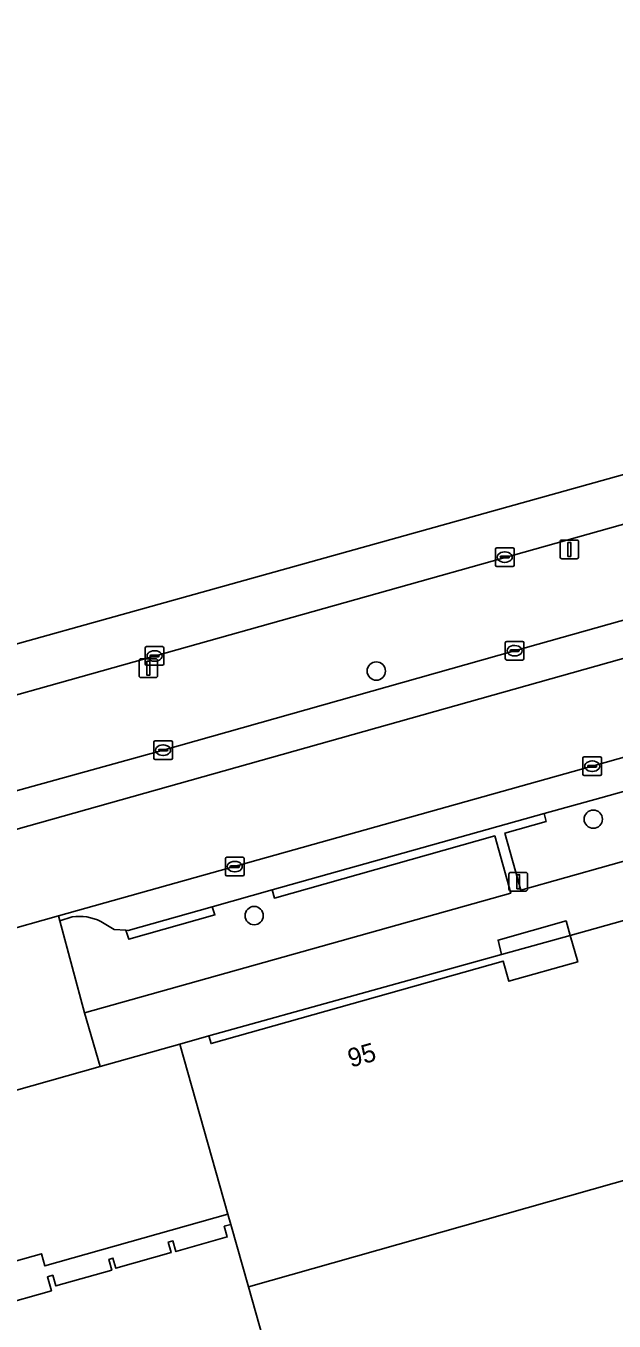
# Model space of a CAD drawing. Extents: x 159680 to 160786, y 387323 to 388340.
# Drawn here: x 159778.2 to 159809.7, y 388163.8 to 388233.1 of the extents above; entities that cross this region are included whole.
import ezdxf

# ---------------------------------------------------------------- set-up
doc = ezdxf.new("R2010")
doc.units = 0
for name, color, linetype in [('IMGEO_Berm_groen', 7, 'Continuous'), ('IMGEO_Boom', 7, 'Continuous'), ('IMGEO_Groenvoorziening', 7, 'Continuous'), ('IMGEO_Kolk', 7, 'Continuous'), ('IMGEO_Lichtmast', 7, 'Continuous'), ('IMGEO_Pand', 7, 'Continuous'), ('IMGEO_Pand_nummerreeks', 7, 'Continuous'), ('IMGEO_Pand_overbouw', 7, 'Continuous'), ('IMGEO_Parkeervlak_open', 7, 'Continuous'), ('IMGEO_Rijbaan_lokaal_open', 7, 'Continuous'), ('IMGEO_Rijbaan_regionaal_gesloten', 7, 'Continuous'), ('IMGEO_Verkeersbordpaal', 7, 'Continuous'), ('IMGEO_Voetpad_open', 7, 'Continuous')]:
    doc.layers.add(name, color=color, linetype=linetype)

msp = doc.modelspace()

# ---------------------------------------------------------------- linework, layer by layer
at = {"layer": 'IMGEO_Berm_groen'}
for points in [[(159920.962, 388232.427), (159919.6, 388237.172), (159716.247, 388179.993)], [(159752.583, 388183.497), (159752.167, 388185.012), (159768.684, 388189.645), (159785.592, 388194.317), (159804.409, 388199.642), (159825.126, 388205.478), (159845.859, 388211.321), (159866.616, 388217.142), (159886.436, 388222.745), (159891.938, 388224.314)]]:
    msp.add_lwpolyline(points, dxfattribs=at)
at = {"layer": 'IMGEO_Boom'}
for centre in [(159797.001, 388198.552), (159808.618, 388190.623), (159790.464, 388185.463)]:
    msp.add_circle(centre, 0.489, dxfattribs=at)
at = {"layer": 'IMGEO_Groenvoorziening'}
for points in [[(159819.69, 388191.76), (159819.005, 388194.105), (159810.488, 388191.713), (159810.361, 388192.138), (159809.024, 388191.774), (159805.984, 388190.92), (159806.089, 388190.5), (159803.886, 388189.879), (159804.744, 388186.824), (159819.205, 388190.886)], [(159780.728, 388185.388), (159780.065, 388185.175), (159781.381, 388180.261), (159804.201, 388186.672), (159803.344, 388189.726), (159791.55, 388186.398), (159791.436, 388186.838), (159788.22, 388185.935), (159788.364, 388185.498), (159783.745, 388184.195), (159783.589, 388184.683), (159782.973, 388184.723), (159782.255, 388185.142)]]:
    msp.add_lwpolyline(points, dxfattribs=at)
msp.add_arc((159781.126, 388182.997), 2.424, 62.24403, 99.45251, dxfattribs=at)
at = {"layer": 'IMGEO_Kolk'}
for p, q in [((159803.381, 388204.227), (159803.381, 388205.079)), ((159803.456, 388205.153), (159804.308, 388205.153)), ((159803.869, 388204.933), (159803.894, 388204.933)), ((159804.382, 388205.079), (159804.382, 388204.227)), ((159804.308, 388204.153), (159803.456, 388204.153)), ((159803.64, 388204.647), (159803.64, 388204.659)), ((159804.078, 388204.61), (159803.68, 388204.61)), ((159803.683, 388204.696), (159804.081, 388204.696)), ((159803.892, 388204.373), (159803.867, 388204.373)), ((159804.124, 388204.659), (159804.124, 388204.647)), ((159803.908, 388199.217), (159803.908, 388200.069)), ((159803.983, 388200.143), (159804.835, 388200.143)), ((159804.396, 388199.923), (159804.421, 388199.923)), ((159804.909, 388200.069), (159804.909, 388199.217)), ((159784.629, 388198.935), (159784.629, 388199.787)), ((159784.704, 388199.861), (159785.556, 388199.861)), ((159784.888, 388199.355), (159784.888, 388199.367)), ((159785.326, 388199.318), (159784.928, 388199.318)), ((159784.931, 388199.404), (159785.329, 388199.404)), ((159785.117, 388199.641), (159785.142, 388199.641)), ((159785.372, 388199.367), (159785.372, 388199.355)), ((159785.63, 388199.787), (159785.63, 388198.935)), ((159804.167, 388199.637), (159804.167, 388199.649)), ((159804.605, 388199.6), (159804.207, 388199.6)), ((159804.21, 388199.686), (159804.608, 388199.686)), ((159804.419, 388199.363), (159804.394, 388199.363)), ((159804.651, 388199.649), (159804.651, 388199.637)), ((159785.556, 388198.861), (159784.704, 388198.861)), ((159785.14, 388199.081), (159785.115, 388199.081)), ((159804.835, 388199.143), (159803.983, 388199.143)), ((159785.09, 388193.892), (159785.09, 388194.744)), ((159785.165, 388194.818), (159786.017, 388194.818)), ((159785.392, 388194.361), (159785.79, 388194.361)), ((159785.578, 388194.598), (159785.603, 388194.598)), ((159786.091, 388194.744), (159786.091, 388193.892)), ((159786.017, 388193.818), (159785.165, 388193.818)), ((159785.349, 388194.312), (159785.349, 388194.324)), ((159785.787, 388194.275), (159785.389, 388194.275)), ((159785.601, 388194.038), (159785.576, 388194.038)), ((159785.833, 388194.324), (159785.833, 388194.312)), ((159808.061, 388193.033), (159808.061, 388193.885)), ((159808.136, 388193.959), (159808.988, 388193.959)), ((159808.549, 388193.739), (159808.574, 388193.739)), ((159809.062, 388193.885), (159809.062, 388193.033)), ((159808.988, 388192.959), (159808.136, 388192.959)), ((159808.32, 388193.453), (159808.32, 388193.465)), ((159808.758, 388193.416), (159808.36, 388193.416)), ((159808.363, 388193.502), (159808.761, 388193.502)), ((159808.572, 388193.179), (159808.547, 388193.179)), ((159808.804, 388193.465), (159808.804, 388193.453)), ((159788.927, 388187.659), (159788.927, 388188.511)), ((159789.002, 388188.585), (159789.854, 388188.585)), ((159789.229, 388188.128), (159789.627, 388188.128)), ((159789.415, 388188.365), (159789.44, 388188.365)), ((159789.928, 388188.511), (159789.928, 388187.659)), ((159789.854, 388187.585), (159789.002, 388187.585)), ((159789.186, 388188.079), (159789.186, 388188.091)), ((159789.624, 388188.042), (159789.226, 388188.042)), ((159789.438, 388187.805), (159789.413, 388187.805)), ((159789.67, 388188.091), (159789.67, 388188.079))]:
    msp.add_line(p, q, dxfattribs=at)
for points in [[(159803.381, 388204.227), (159803.381, 388205.079)], [(159803.456, 388205.153), (159804.308, 388205.153)], [(159804.382, 388205.079), (159804.382, 388204.227)], [(159804.308, 388204.153), (159803.456, 388204.153)], [(159803.908, 388199.217), (159803.908, 388200.069)], [(159803.983, 388200.143), (159804.835, 388200.143)], [(159804.909, 388200.069), (159804.909, 388199.217)], [(159784.629, 388198.935), (159784.629, 388199.787)], [(159784.704, 388199.861), (159785.556, 388199.861)], [(159785.63, 388199.787), (159785.63, 388198.935)], [(159785.556, 388198.861), (159784.704, 388198.861)], [(159804.835, 388199.143), (159803.983, 388199.143)], [(159785.09, 388193.892), (159785.09, 388194.744)], [(159785.165, 388194.818), (159786.017, 388194.818)], [(159786.091, 388194.744), (159786.091, 388193.892)], [(159786.017, 388193.818), (159785.165, 388193.818)], [(159808.061, 388193.033), (159808.061, 388193.885)], [(159808.136, 388193.959), (159808.988, 388193.959)], [(159809.062, 388193.885), (159809.062, 388193.033)], [(159808.988, 388192.959), (159808.136, 388192.959)], [(159788.927, 388187.659), (159788.927, 388188.511)], [(159789.002, 388188.585), (159789.854, 388188.585)], [(159789.928, 388188.511), (159789.928, 388187.659)], [(159789.854, 388187.585), (159789.002, 388187.585)]]:
    msp.add_lwpolyline(points, dxfattribs=at)
for centre, radius, start, end in [((159803.458, 388205.077), 0.0765, 91.55205, 178.44795), ((159803.458, 388205.077), 0.0765, 91.55205, 178.44795), ((159804.306, 388205.077), 0.0765, 1.55205, 88.44795), ((159804.306, 388205.077), 0.0765, 1.55205, 88.44795), ((159803.458, 388204.229), 0.0765, 181.55205, 268.44795), ((159803.458, 388204.229), 0.0765, 181.55205, 268.44795), ((159803.68, 388204.656), 0.0403, 85.87752, 175.75265), ((159803.677, 388204.646), 0.0366, 178.93798, 274.71019), ((159804.081, 388204.653), 0.043, 264.86636, 352.45326), ((159804.085, 388204.658), 0.0386, 1.73085, 96.63898), ((159804.306, 388204.229), 0.0765, 271.55205, 358.44795), ((159804.306, 388204.229), 0.0765, 271.55205, 358.44795), ((159803.985, 388200.067), 0.0765, 91.55205, 178.44795), ((159803.985, 388200.067), 0.0765, 91.55205, 178.44795), ((159804.833, 388200.067), 0.0765, 1.55205, 88.44795), ((159804.833, 388200.067), 0.0765, 1.55205, 88.44795), ((159784.706, 388199.785), 0.0765, 91.55205, 178.44795), ((159784.706, 388199.785), 0.0765, 91.55205, 178.44795), ((159784.928, 388199.364), 0.0403, 85.87752, 175.75265), ((159784.925, 388199.354), 0.0366, 178.93798, 274.71019), ((159785.329, 388199.361), 0.043, 264.86636, 352.45326), ((159785.333, 388199.366), 0.0386, 1.73085, 96.63898), ((159785.554, 388199.785), 0.0765, 1.55205, 88.44795), ((159785.554, 388199.785), 0.0765, 1.55205, 88.44795), ((159803.985, 388199.219), 0.0765, 181.55205, 268.44795), ((159803.985, 388199.219), 0.0765, 181.55205, 268.44795), ((159804.207, 388199.646), 0.0403, 85.87752, 175.75265), ((159804.204, 388199.636), 0.0366, 178.93798, 274.71019), ((159804.608, 388199.643), 0.043, 264.86636, 352.45326), ((159804.612, 388199.648), 0.0386, 1.73085, 96.63898), ((159804.833, 388199.219), 0.0765, 271.55205, 358.44795), ((159804.833, 388199.219), 0.0765, 271.55205, 358.44795), ((159784.706, 388198.937), 0.0765, 181.55205, 268.44795), ((159784.706, 388198.937), 0.0765, 181.55205, 268.44795), ((159785.554, 388198.937), 0.0765, 271.55205, 358.44795), ((159785.554, 388198.937), 0.0765, 271.55205, 358.44795), ((159785.167, 388194.742), 0.0765, 91.55205, 178.44795), ((159785.167, 388194.742), 0.0765, 91.55205, 178.44795), ((159785.389, 388194.321), 0.0403, 85.87752, 175.75265), ((159785.794, 388194.323), 0.0386, 1.73085, 96.63898), ((159786.015, 388194.742), 0.0765, 1.55205, 88.44795), ((159786.015, 388194.742), 0.0765, 1.55205, 88.44795), ((159785.167, 388193.894), 0.0765, 181.55205, 268.44795), ((159785.167, 388193.894), 0.0765, 181.55205, 268.44795), ((159785.386, 388194.311), 0.0366, 178.93798, 274.71019), ((159785.79, 388194.318), 0.043, 264.86636, 352.45326), ((159786.015, 388193.894), 0.0765, 271.55205, 358.44795), ((159786.015, 388193.894), 0.0765, 271.55205, 358.44795), ((159808.138, 388193.883), 0.0765, 91.55205, 178.44795), ((159808.138, 388193.883), 0.0765, 91.55205, 178.44795), ((159808.986, 388193.883), 0.0765, 1.55205, 88.44795), ((159808.986, 388193.883), 0.0765, 1.55205, 88.44795), ((159808.138, 388193.035), 0.0765, 181.55205, 268.44795), ((159808.138, 388193.035), 0.0765, 181.55205, 268.44795), ((159808.36, 388193.462), 0.0403, 85.87752, 175.75265), ((159808.357, 388193.452), 0.0366, 178.93798, 274.71019), ((159808.761, 388193.459), 0.043, 264.86636, 352.45326), ((159808.765, 388193.464), 0.0386, 1.73085, 96.63898), ((159808.986, 388193.035), 0.0765, 271.55205, 358.44795), ((159808.986, 388193.035), 0.0765, 271.55205, 358.44795), ((159789.004, 388188.509), 0.0765, 91.55205, 178.44795), ((159789.004, 388188.509), 0.0765, 91.55205, 178.44795), ((159789.226, 388188.088), 0.0403, 85.87752, 175.75265), ((159789.631, 388188.09), 0.0386, 1.73085, 96.63898), ((159789.852, 388188.509), 0.0765, 1.55205, 88.44795), ((159789.852, 388188.509), 0.0765, 1.55205, 88.44795), ((159789.004, 388187.661), 0.0765, 181.55205, 268.44795), ((159789.004, 388187.661), 0.0765, 181.55205, 268.44795), ((159789.223, 388188.078), 0.0366, 178.93798, 274.71019), ((159789.627, 388188.085), 0.043, 264.86636, 352.45326), ((159789.852, 388187.661), 0.0765, 271.55205, 358.44795), ((159789.852, 388187.661), 0.0765, 271.55205, 358.44795)]:
    msp.add_arc(centre, radius, start, end, dxfattribs=at)
for centre, major_axis, ratio, start_param, end_param in [((159803.868, 388204.653), (-0.387, 0.002), 0.722429, 4.712389, 7.853982), ((159803.893, 388204.653), (-0.39, 0.002), 0.717154, 1.570796, 4.712389), ((159804.395, 388199.643), (-0.387, 0.002), 0.722429, 4.712389, 7.853982), ((159804.42, 388199.643), (-0.39, 0.002), 0.717154, 1.570796, 4.712389), ((159785.116, 388199.361), (-0.387, 0.002), 0.722429, 4.712389, 7.853982), ((159785.141, 388199.361), (-0.39, 0.002), 0.717154, 1.570796, 4.712389), ((159785.577, 388194.318), (-0.387, 0.002), 0.722429, 4.712389, 7.853982), ((159785.602, 388194.318), (-0.39, 0.002), 0.717154, 1.570796, 4.712389), ((159808.548, 388193.459), (-0.387, 0.002), 0.722429, 4.712389, 7.853982), ((159808.573, 388193.459), (-0.39, 0.002), 0.717154, 1.570796, 4.712389), ((159789.414, 388188.085), (-0.387, 0.002), 0.722429, 4.712389, 7.853982), ((159789.439, 388188.085), (-0.39, 0.002), 0.717154, 1.570796, 4.712389)]:
    msp.add_ellipse(centre, major_axis=major_axis, ratio=ratio, start_param=start_param, end_param=end_param, dxfattribs=at)
at = {"layer": 'IMGEO_Lichtmast'}
for p, q in [((159806.841, 388204.666), (159806.841, 388205.466)), ((159806.841, 388205.466), (159806.841, 388204.666)), ((159806.941, 388205.566), (159807.731, 388205.566)), ((159807.731, 388205.566), (159806.941, 388205.566)), ((159807.831, 388205.466), (159807.831, 388204.666)), ((159807.831, 388204.666), (159807.831, 388205.466)), ((159807.731, 388204.566), (159806.941, 388204.566)), ((159806.941, 388204.566), (159807.731, 388204.566)), ((159784.403, 388199.208), (159785.193, 388199.208)), ((159785.193, 388199.208), (159784.403, 388199.208)), ((159784.303, 388198.308), (159784.303, 388199.108)), ((159784.303, 388199.108), (159784.303, 388198.308)), ((159785.293, 388199.108), (159785.293, 388198.308)), ((159785.293, 388198.308), (159785.293, 388199.108)), ((159785.193, 388198.208), (159784.403, 388198.208)), ((159784.403, 388198.208), (159785.193, 388198.208))]:
    msp.add_line(p, q, dxfattribs=at)
for points in [[(159807.261, 388205.441), (159807.411, 388205.441), (159807.411, 388204.691), (159807.261, 388204.691), (159807.261, 388205.441)], [(159784.723, 388199.083), (159784.873, 388199.083), (159784.873, 388198.333), (159784.723, 388198.333), (159784.723, 388199.083)]]:
    msp.add_lwpolyline(points, dxfattribs=at)
for centre, start, end in [((159806.941, 388205.466), 90, 180), ((159806.941, 388205.466), 90, 180), ((159807.731, 388205.466), 0, 90), ((159807.731, 388205.466), 360, 90), ((159806.941, 388204.666), 180, 270), ((159806.941, 388204.666), 180, 270), ((159807.731, 388204.666), 270, 0), ((159807.731, 388204.666), 270, 0), ((159784.403, 388199.108), 90, 180), ((159784.403, 388199.108), 90, 180), ((159785.193, 388199.108), 0, 90), ((159785.193, 388199.108), 360, 90), ((159784.403, 388198.308), 180, 270), ((159784.403, 388198.308), 180, 270), ((159785.193, 388198.308), 270, 0), ((159785.193, 388198.308), 270, 0)]:
    msp.add_arc(centre, 0.1, start, end, dxfattribs=at)
at = {"layer": 'IMGEO_Pand'}
for points in [[(159810.788, 388184.755), (159810.63, 388185.313), (159807.388, 388184.396), (159807.786, 388182.987), (159804.103, 388181.946), (159803.796, 388183.031), (159788.159, 388178.613), (159788.043, 388179.024), (159786.488, 388178.585), (159789.062, 388169.474), (159789.216, 388168.927), (159790.158, 388165.594), (159814.275, 388172.417)], [(159814.275, 388172.417), (159790.158, 388165.594), (159793.826, 388152.611), (159795.605, 388146.314), (159799.791, 388131.499), (159805.048, 388112.894), (159820.275, 388117.209), (159829.165, 388119.728), (159823.152, 388141.005), (159819.726, 388153.128)]]:
    msp.add_lwpolyline(points, close=True, dxfattribs=at)
msp.add_lwpolyline([(159768.044, 388145.288), (159793.826, 388152.611), (159790.158, 388165.594), (159789.216, 388168.927), (159788.863, 388168.828), (159789.024, 388168.257), (159786.274, 388167.48), (159786.113, 388168.051), (159785.867, 388167.981), (159786.025, 388167.421), (159783.057, 388166.583), (159782.904, 388167.124), (159782.674, 388167.059), (159782.835, 388166.489), (159779.838, 388165.642), (159779.678, 388166.209), (159779.395, 388166.129), (159779.606, 388165.382), (159776.681, 388164.555)], dxfattribs=at)
at = {"layer": 'IMGEO_Pand_overbouw'}
msp.add_lwpolyline([(159776.681, 388164.555), (159779.606, 388165.382), (159779.395, 388166.129), (159779.678, 388166.209), (159779.838, 388165.642), (159782.835, 388166.489), (159782.674, 388167.059), (159782.904, 388167.124), (159783.057, 388166.583), (159786.025, 388167.421), (159785.867, 388167.981), (159786.113, 388168.051), (159786.274, 388167.48), (159789.024, 388168.257), (159788.863, 388168.828), (159789.216, 388168.927), (159789.062, 388169.474), (159779.264, 388166.706), (159779.078, 388167.362), (159776.135, 388166.531)], dxfattribs=at)
at = {"layer": 'IMGEO_Parkeervlak_open'}
for points in [[(159891.938, 388224.314), (159886.436, 388222.745), (159866.616, 388217.142), (159845.859, 388211.321), (159825.126, 388205.478), (159804.409, 388199.642), (159785.592, 388194.317), (159768.684, 388189.645), (159752.167, 388185.012), (159752.583, 388183.497)], [(159752.279, 388182.917), (159895.708, 388223.298), (159894.565, 388223.603), (159893.402, 388224.172)], [(159853.481, 388205.795), (159854.08, 388205.965), (159853.995, 388206.283), (159829.06, 388199.251), (159808.558, 388193.46), (159779.983, 388185.443), (159780.065, 388185.175), (159780.728, 388185.388)], [(159782.255, 388185.142), (159782.973, 388184.723), (159783.589, 388184.683), (159783.719, 388184.672), (159788.22, 388185.935), (159791.436, 388186.838), (159805.984, 388190.92), (159809.024, 388191.774), (159810.361, 388192.138), (159826.794, 388196.764), (159829.412, 388197.501), (159845.439, 388202.012), (159848.915, 388202.991), (159851.294, 388203.66), (159851.495, 388203.741), (159851.908, 388204.123), (159852.307, 388204.794)], [(159776.681, 388164.555), (159779.606, 388165.382), (159779.395, 388166.129), (159779.678, 388166.209), (159779.838, 388165.642), (159782.835, 388166.489), (159782.674, 388167.059), (159782.904, 388167.124), (159783.057, 388166.583), (159786.025, 388167.421), (159785.867, 388167.981), (159786.113, 388168.051), (159786.274, 388167.48), (159789.024, 388168.257), (159788.863, 388168.828), (159789.216, 388168.927), (159789.062, 388169.474), (159786.488, 388178.585), (159782.224, 388177.38), (159775.835, 388175.578)]]:
    msp.add_lwpolyline(points, dxfattribs=at)
msp.add_arc((159781.126, 388182.997), 2.424, 62.24403, 99.45251, dxfattribs=at)
at = {"layer": 'IMGEO_Rijbaan_lokaal_open'}
for points in [[(159990.313, 388250), (159958.999, 388241.151), (159958.522, 388241.005), (159950.795, 388238.836), (159938.589, 388235.41), (159938.057, 388235.259), (159918.811, 388229.861), (159918.074, 388229.639), (159896.382, 388223.491), (159895.708, 388223.298), (159752.279, 388182.917), (159750.225, 388182.349), (159750.033, 388182.294), (159740.394, 388179.542), (159738.197, 388178.962), (159726.603, 388175.761), (159726.396, 388175.68), (159725.585, 388175.389)], [(159723.456, 388169.745), (159723.633, 388169.719), (159724.653, 388169.975), (159726.472, 388170.472), (159748.553, 388176.646), (159753.855, 388178.128), (159770.727, 388182.846), (159773.651, 388183.666), (159779.983, 388185.443), (159808.558, 388193.46), (159829.06, 388199.251), (159853.995, 388206.283), (159858.217, 388207.473), (159948.035, 388232.803)]]:
    msp.add_lwpolyline(points, dxfattribs=at)
at = {"layer": 'IMGEO_Rijbaan_regionaal_gesloten'}
msp.add_lwpolyline([(159702.179, 388176.035), (159702.945, 388176.248), (159704.075, 388176.561), (159705.928, 388177.01), (159716.247, 388179.993), (159919.6, 388237.172), (159948.924, 388245.417), (160022.709, 388266.163), (160022.114, 388268.189), (159861.579, 388223.398), (159698.928, 388178.017)], dxfattribs=at)
at = {"layer": 'IMGEO_Verkeersbordpaal'}
for p, q in [((159804.107, 388186.877), (159804.107, 388187.677)), ((159804.107, 388187.677), (159804.107, 388186.877)), ((159804.207, 388187.777), (159804.997, 388187.777)), ((159804.997, 388187.777), (159804.207, 388187.777)), ((159805.097, 388187.677), (159805.097, 388186.877)), ((159805.097, 388186.877), (159805.097, 388187.677)), ((159804.997, 388186.777), (159804.207, 388186.777)), ((159804.207, 388186.777), (159804.997, 388186.777))]:
    msp.add_line(p, q, dxfattribs=at)
msp.add_lwpolyline([(159804.527, 388187.652), (159804.677, 388187.652), (159804.677, 388186.902), (159804.527, 388186.902), (159804.527, 388187.652)], dxfattribs=at)
for centre, start, end in [((159804.207, 388187.677), 90, 180), ((159804.207, 388187.677), 90, 180), ((159804.997, 388187.677), 0, 90), ((159804.997, 388187.677), 360, 90), ((159804.207, 388186.877), 180, 270), ((159804.207, 388186.877), 180, 270), ((159804.997, 388186.877), 270, 0), ((159804.997, 388186.877), 270, 0)]:
    msp.add_arc(centre, 0.1, start, end, dxfattribs=at)
at = {"layer": 'IMGEO_Voetpad_open'}
msp.add_lwpolyline([(159819.205, 388190.886), (159804.744, 388186.824), (159803.886, 388189.879), (159806.089, 388190.5), (159805.984, 388190.92), (159791.436, 388186.838), (159791.55, 388186.398), (159803.344, 388189.726), (159804.201, 388186.672), (159781.381, 388180.261), (159782.224, 388177.38), (159786.488, 388178.585), (159788.043, 388179.024), (159803.713, 388183.375), (159803.525, 388184.152), (159807.166, 388185.181), (159807.388, 388184.396), (159810.63, 388185.313)], dxfattribs=at)
for points in [[(159781.381, 388180.261), (159780.065, 388185.175), (159779.983, 388185.443), (159773.651, 388183.666), (159773.727, 388183.404), (159773.861, 388182.944), (159774.262, 388181.568), (159774.999, 388178.482), (159775.835, 388175.578), (159782.224, 388177.38)], [(159783.589, 388184.683), (159783.745, 388184.195), (159788.364, 388185.498), (159788.22, 388185.935), (159783.719, 388184.672)], [(159807.166, 388185.181), (159803.525, 388184.152), (159803.713, 388183.375), (159807.388, 388184.396)], [(159788.043, 388179.024), (159788.159, 388178.613), (159803.796, 388183.031), (159804.103, 388181.946), (159807.786, 388182.987), (159807.388, 388184.396), (159803.713, 388183.375)]]:
    msp.add_lwpolyline(points, close=True, dxfattribs=at)

# ---------------------------------------------------------------- texts
at = {"layer": 'IMGEO_Pand_nummerreeks'}
msp.add_text('95', height=1, rotation=15.77684, dxfattribs=at).set_placement((159795.639, 388177.318))

doc.saveas('drawing.dxf')
